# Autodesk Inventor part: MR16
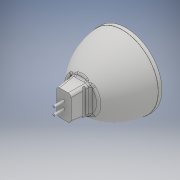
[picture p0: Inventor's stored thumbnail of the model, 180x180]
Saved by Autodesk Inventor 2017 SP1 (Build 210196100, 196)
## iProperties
Created: 2016-12
Part Number: MR16
Material: Generic
Document SubType Name: Modeling
Designer: HP_ELITE
Density: 1 g/cm^3
Appearance: Default
Author: HP_ELITE
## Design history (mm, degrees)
sketch "Sketch1"
  geometry: L1 (0, 0)-(0, 31.15); L2 (0, 31.15)-(25, 31.15); L3 (25, 31.15)-(25, 28.65); L4 (25, 28.65)-(24.889, 28.65); L5 (11.75, 0)-(0, 0); A1 r 45 centre (-19.994, 31.896) between (11.75, 0) and (25, 31.15)
  constraints: 10 end point, 3 point on circle, 2 perpendicular, 2 vertical, 1 centre point, 1 horizontal
  dimensions: "d0" = 31.15 distance of L1.start L1.end; "d1" = 25 distance of L1.end L2.end; "d2" = 2.5 distance of L2.end L3.end; "d3" = 11.75 distance of L5.start L1.start; "d4" = 45 radius of A1
revolve "Revolution1" sketch "Sketch1" stored, may be unused: angle "d5" = 90 deg
sketch "Sketch2"
  geometry: L1 (0, 0)-(-12.32, 0); L2 (-12.32, 8.875)-(-12.32, -8.875); L3 (-12.32, 8.875)-(0, 10); L4 (0, 10)-(0, -10); L5 (0, -10)-(-12.32, -8.875); L6 (31.15, 25)-(31.15, -25) reference
  constraints: 10 end point, 2 midpoint, 2 vertical, 1 horizontal
  dimensions: "d7" = 12.32 distance of L1.end L1.start; "d8" = 17.75 distance of L2.start L2.end; "d9" = 20 distance of L3.end L4.end; "d10" = 43.47 distance between parallel lines of L2 L6 (derived)
extrude "Extrusion1" join sketch "Sketch2" stored distance "d11" = 12.3; taper "d12" = 0 deg
sketch "Sketch3"
  geometry: L1 (-6.15, -12.32)-(6.15, -12.32) reference; L2 (5, -12.32)-(-5, -12.32); L3 (5, -12.32)-(6.15, -12.32); L4 (-5, -12.32)-(-6.15, -12.32); L5 (-6.15, 0)-(6.15, 0); L6 (-6.15, 0)-(-6.15, -12.32) reference; L7 (-6.15, -12.32)-(-6.15, 0) reference; L8 (-6.15, -12.32)-(6.15, -12.32) reference; L9 (6.15, 0)-(6.15, -12.32) reference; L10 (-6.15, 0)-(6.15, 0) reference; L11 (-6.15, -12.32)-(-6.15, 0) reference; L12 (6.15, 0)-(5, -12.32); L13 (-5, -12.32)-(-6.15, 0); C1 r 0.934 at (-5.796, -3.79); A1 r 0.934 centre (5.796, -3.79) between (5.709, -4.72) and (5.883, -2.86); 2 further points
  constraints: 12 end point, 6 point on line, 3 collinear, 2 centre point, 2 midpoint, 2 point on circle, 1 equal radius, 1 horizontal alignment
  dimensions: "d13" = 10 distance of L2.start L2.end; "d14" = 9.46 distance from line of L1 A1.end; "d15" = 7.6 distance from line of L1 A1.start
extrude "Extrusion2" cut sketch "Sketch3" stored distance "d16" = 12.3; taper "d17" = 0 deg
fillet "Fillet1" dims "d18" = 2
fillet "Fillet2" dims "d19" = 1.5
fillet "Fillet3" dims "d20" = 3
sketch "Sketch4"
  geometry: L1 (3.008, 6.375)-(3.008, 11.375); C1 r 0.725 at (3.008, 6.375); C2 r 0.725 at (3.008, 11.375); 2 further points
  constraints: 3 coincident, 2 centre point, 2 end point, 1 equal radius, 1 midpoint, 1 vertical
  dimensions: "d21" = 5 distance of L1.start L1.end; "d22" = 1.45 diameter of C1
extrude "Extrusion3" join sketch "Sketch4" distance "d23" = 7; taper "d24" = 0 deg
body "Solid1"
node "Projected Loop1"
node "Projected Loop2"
